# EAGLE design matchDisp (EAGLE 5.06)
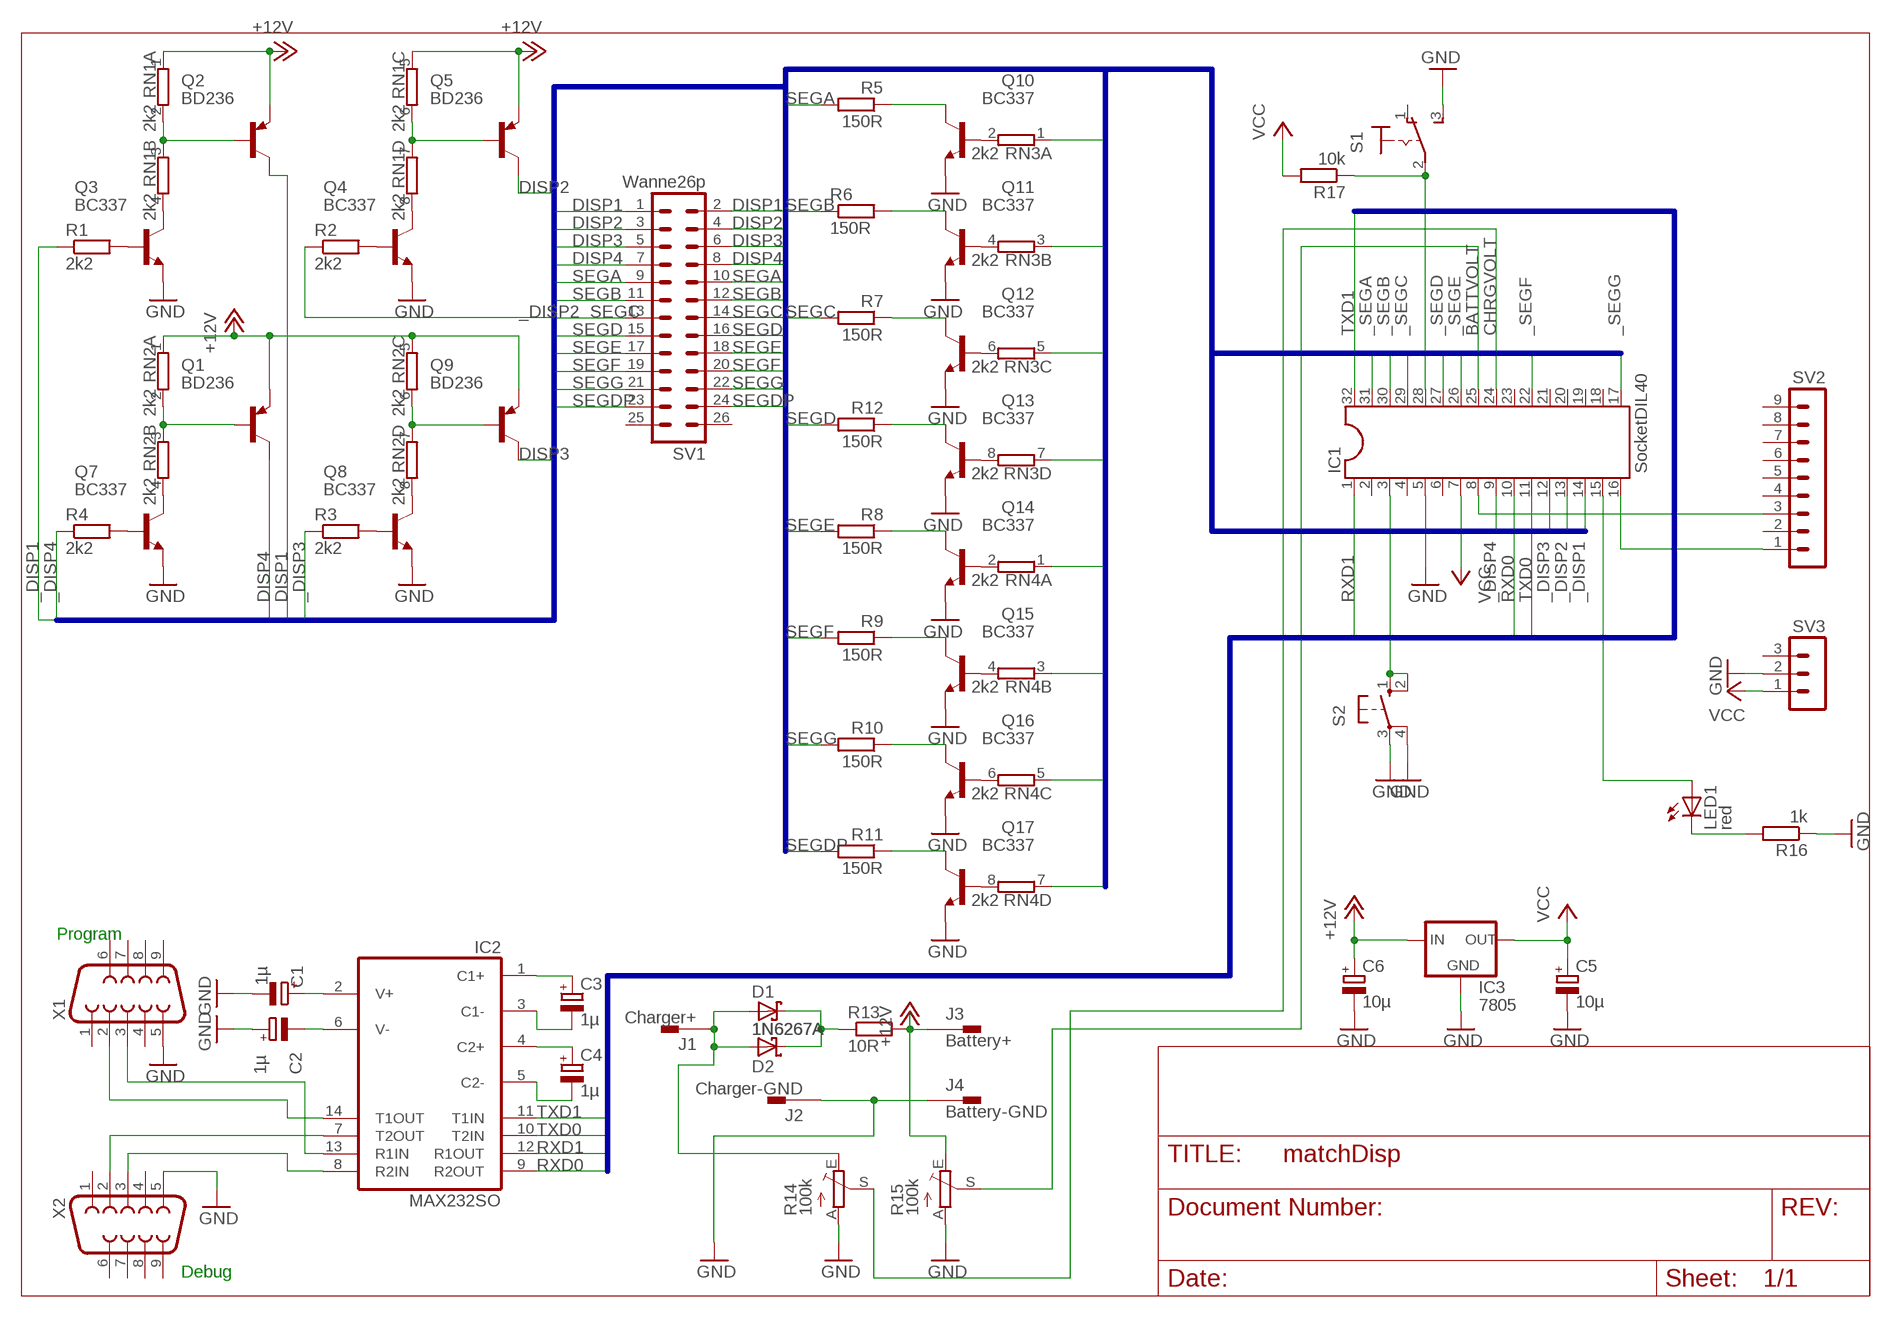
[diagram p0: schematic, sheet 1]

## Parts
C1  1µ  CPOL-EUE2.5-6  [E2,5-6]
C2  1µ  CPOL-EUE2.5-6  [E2,5-6]
C3  1µ  CPOL-EUE2.5-6  [E2,5-6]
C4  1µ  CPOL-EUE2.5-6  [E2,5-6]
C5  10µ  CPOL-EUE2.5-6  [E2,5-6]
C6  10µ  CPOL-EUE2.5-6  [E2,5-6]
D1  1N6267A  [C4111-15]
D2  1N6267A  [C4111-15]
IC1  SocketDIL40  DIL32  [DIL32]
IC2  MAX232SO  [SO16]
IC3  7805  78XXS  [78XXS]
J1  Charger+  PIN262409-1  [62409-1]
J2  Charger-GND  PIN262409-1  [62409-1]
J3  Battery+  PIN262409-1  [62409-1]
J4  Battery-GND  PIN262409-1  [62409-1]
LED1  red  LEDSFH480  [SFH480]
Q1  BD236  [TO126]
Q2  BD236  [TO126]
Q3  BC337  [TO92]
Q4  BC337  [TO92]
Q5  BD236  [TO126]
Q7  BC337  [TO92]
Q8  BC337  [TO92]
Q9  BD236  [TO126]
Q10  BC337  [TO92]
Q11  BC337  [TO92]
Q12  BC337  [TO92]
Q13  BC337  [TO92]
Q14  BC337  [TO92]
Q15  BC337  [TO92]
Q16  BC337  [TO92]
Q17  BC337  [TO92]
R1  2k2  R-EU_0204/2V  [0204V]
R2  2k2  R-EU_0204/2V  [0204V]
R3  2k2  R-EU_0204/2V  [0204V]
R4  2k2  R-EU_0204/2V  [0204V]
R5  150R  R-EU_0204/2V  [0204V]
R6  150R  R-EU_0204/2V  [0204V]
R7  150R  R-EU_0204/2V  [0204V]
R8  150R  R-EU_0204/2V  [0204V]
R9  150R  R-EU_0204/2V  [0204V]
R10  150R  R-EU_0204/2V  [0204V]
R11  150R  R-EU_0204/2V  [0204V]
R12  150R  R-EU_0204/2V  [0204V]
R13  10R  R-EU_0817/22  [P0817/22]
R14  100k  TRIM_EU-B64Y  [B64Y]
R15  100k  TRIM_EU-B64Y  [B64Y]
R16  1k  R-EU_0411/12  [0411/12]
R17  10k  R-EU_0411/12  [0411/12]
RN1  2k2  E4R  [SIL8]
RN2  2k2  E4R  [SIL8]
RN3  2k2  E4R  [SIL8]
RN4  2k2  E4R  [SIL8]
S1  M9040P  [M9040P]
S2  10-XX  [B3F-10XX]
SV1  Wanne26p  ML26  [ML26]
SV2  MA09-1  [MA09-1]
SV3  MA03-1  [MA03-1]
X1  F09VP  [F09VP]
X2  F09VP  [F09VP]

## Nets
+12V: C6.+ IC3.IN J3.A1 Q1.1(E) Q2.1(E) Q5.1(E) Q9.1(E) R13.2 R15.E RN1.1 RN1.5 RN2.1 RN2.5
_DISP1: IC1.14 R1.1
_DISP2: IC1.13 R2.1
_DISP3: IC1.12 R3.1
_DISP4: IC1.9 R4.1
_SEGA: IC1.31 RN3.1
_SEGB: IC1.30 RN3.3
_SEGC: IC1.29 RN3.5
_SEGD: IC1.27 RN3.7
_SEGDP: RN4.7
_SEGE: IC1.26 RN4.1
_SEGF: IC1.22 RN4.3
_SEGG: IC1.17 RN4.5
BATTVOLT: IC1.25 R15.S
CHRGVOLT: IC1.24 R14.S
DISP1: Q2.2(C) SV1.1 SV1.2
DISP2: Q5.2(C) SV1.3 SV1.4
DISP3: Q9.2(C) SV1.5 SV1.6
DISP4: Q1.2(C) SV1.7 SV1.8
GND: C1.- C2.+ C5.- C6.- IC1.5 IC3.GND J2.A1 J4.A1 Q3.1(E) Q4.1(E) Q7.1(E) Q8.1(E) Q10.1(E) Q11.1(E) Q12.1(E) Q13.1(E) Q14.1(E) Q15.1(E) Q16.1(E) Q17.1(E) R14.A R15.A R16.1 S1.3(S) S2.3(P) S2.4(P1) SV3.2 X1.5 X2.5
N$1: IC1.15 LED1.A
N$2: Q3.2(B) R1.2
N$3: Q3.3(C) RN1.4
N$4: LED1.K(C) R16.2
N$5: Q2.3(B) RN1.2 RN1.3
N$6: D1.C D2.C R13.1
N$7: Q4.3(C) RN1.8
N$8: Q5.3(B) RN1.6 RN1.7
N$9: Q13.3(C) R12.1
N$10: C1.+ IC2.2(V+)
N$11: C2.- IC2.6(V-)
N$12: Q1.3(B) RN2.2 RN2.3
N$13: Q4.2(B) R2.2
N$14: Q8.2(B) R3.2
N$15: Q7.2(B) R4.2
N$16: Q10.2(B) RN3.2
N$17: Q11.2(B) RN3.4
N$18: Q12.2(B) RN3.6
N$19: C3.+ IC2.1(C1+)
N$20: Q9.3(B) RN2.6 RN2.7
N$21: C3.- IC2.3(C1-)
N$22: C4.+ IC2.4(C2+)
N$23: Q7.3(C) RN2.4
N$24: Q8.3(C) RN2.8
N$25: Q13.2(B) RN3.8
N$26: Q14.2(B) RN4.2
N$27: Q15.2(B) RN4.4
N$28: Q16.2(B) RN4.6
N$29: Q17.2(B) RN4.8
N$30: Q10.3(C) R5.1
N$31: Q17.3(C) R11.1
N$32: Q16.3(C) R10.1
N$33: Q15.3(C) R9.1
N$34: Q14.3(C) R8.1
N$35: C4.- IC2.5(C2-)
N$36: Q12.3(C) R7.1
N$37: Q11.3(C) R6.2
N$38: IC2.13(R1IN) X1.3
N$39: IC2.14(T1OUT) X1.2
N$40: IC2.7(T2OUT) X2.2
N$41: IC2.8(R2IN) X2.3
N$42: IC1.3 S2.1(S) S2.2(S1)
N$43: IC1.28 R17.1 S1.2(P)
N$44: IC1.16 SV2.1
N$45: IC1.8 SV2.3
N$46: D1.A D2.A J1.A1 R14.E
RXD0: IC1.10 IC2.9(R2OUT)
RXD1: IC1.1 IC2.12(R1OUT)
SEGA: R5.2 SV1.9 SV1.10
SEGB: R6.1 SV1.11 SV1.12
SEGC: R7.2 SV1.13 SV1.14
SEGD: R12.2 SV1.15 SV1.16
SEGDP: R11.2 SV1.23 SV1.24
SEGE: R8.2 SV1.17 SV1.18
SEGF: R9.2 SV1.19 SV1.20
SEGG: R10.2 SV1.21 SV1.22
TXD0: IC1.11 IC2.10(T2IN)
TXD1: IC1.32 IC2.11(T1IN)
VCC: C5.+ IC1.7 IC3.OUT R17.2 SV3.1
Unconnected: IC1.2 IC1.4 IC1.6 IC1.18 IC1.19 IC1.20 IC1.21 IC1.23 J1.A2(1.1) J2.A2(1.1) J3.A2(1.1) J4.A2(1.1) S1.1(O) SV1.25 SV1.26 SV2.2 SV2.4 SV2.5 SV2.6 SV2.7 SV2.8 SV2.9 SV3.3 X1.1 X1.4 X1.6 X1.7 X1.8 X1.9 X2.1 X2.4 X2.6 X2.7 X2.8 X2.9

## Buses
DRVBUS:_DISP1,DISP1,_DISP2,DISP2,_DISP3,DISP3,_DISP4,DISP4,_SEGA,SEGA,_SEGB,SEGB,_SEGC,SEGC,_SEGD,SEGD,_SEGE,SEGE,_SEGF,SEGF,_SEGG,SEGG,_SEGDP,SEGDP
UART:RXD0,TXD0,RXD1,TXD1

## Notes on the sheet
- Program
- Debug

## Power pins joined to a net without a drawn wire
GND: IC2.15(GND)
VCC: IC2.16(VCC)

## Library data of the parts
C1-C6 = rcl:CPOL-EU: POLARIZED CAPACITOR, European symbol
D1 D2 = diode:1N6267A: DIODE
IC1 = ic-package:DIL32: Dual In Line
IC2 = maxim:MAX232: RS232 TRANSEIVER
IC3 = v-reg:78XXS: VOLTAGE REGULATOR
J1-J4 = con-faston:PIN2: Flachstecker Typ Tyco/Electronics/AMP TAB, FASTON
LED1 = led:LED: LED
Q1 Q2 Q5 Q9 = transistor-pnp:BD236: PNP Transistor
Q3 Q7 Q10-Q17 = transistor-npn:BC337*: NPN Transistor
Q4 Q8 = transistor-neu-to92:BC337: NPN TRANSISTOR
R1-R12 R16 R17 = rcl:R-EU_: RESISTOR, European symbol
R13 = resistor:R-EU_: RESISTOR, European symbol
R14 R15 = pot:TRIM_EU-: POTENTIOMETER
RN1-RN4 = resistor-sil:E4R: SIL RESISTOR
S1 = switch:M9040P: TOGGLE SWITCH Marquardt
S2 = switch-omron:10-XX: OMRON SWITCH
SV1 = con-harting-ml:ML26: HARTING
SV2 = con-lstb:MA09-1: PIN HEADER
SV3 = con-lstb:MA03-1: PIN HEADER
X1 X2 = con-subd:F09: SUB-D

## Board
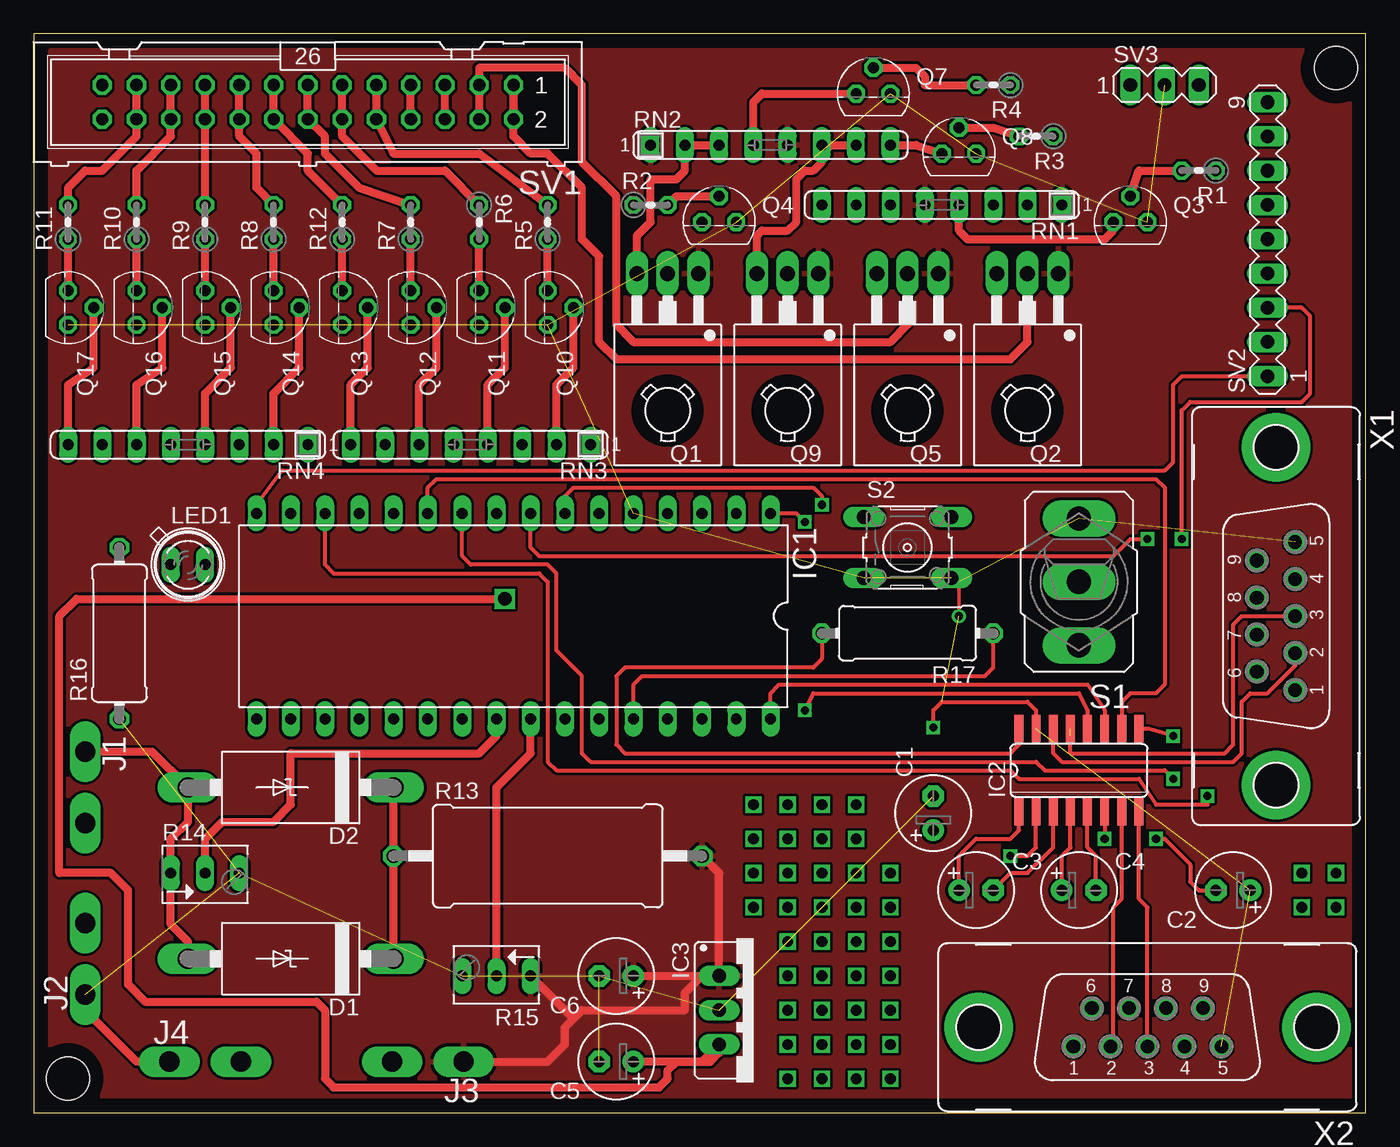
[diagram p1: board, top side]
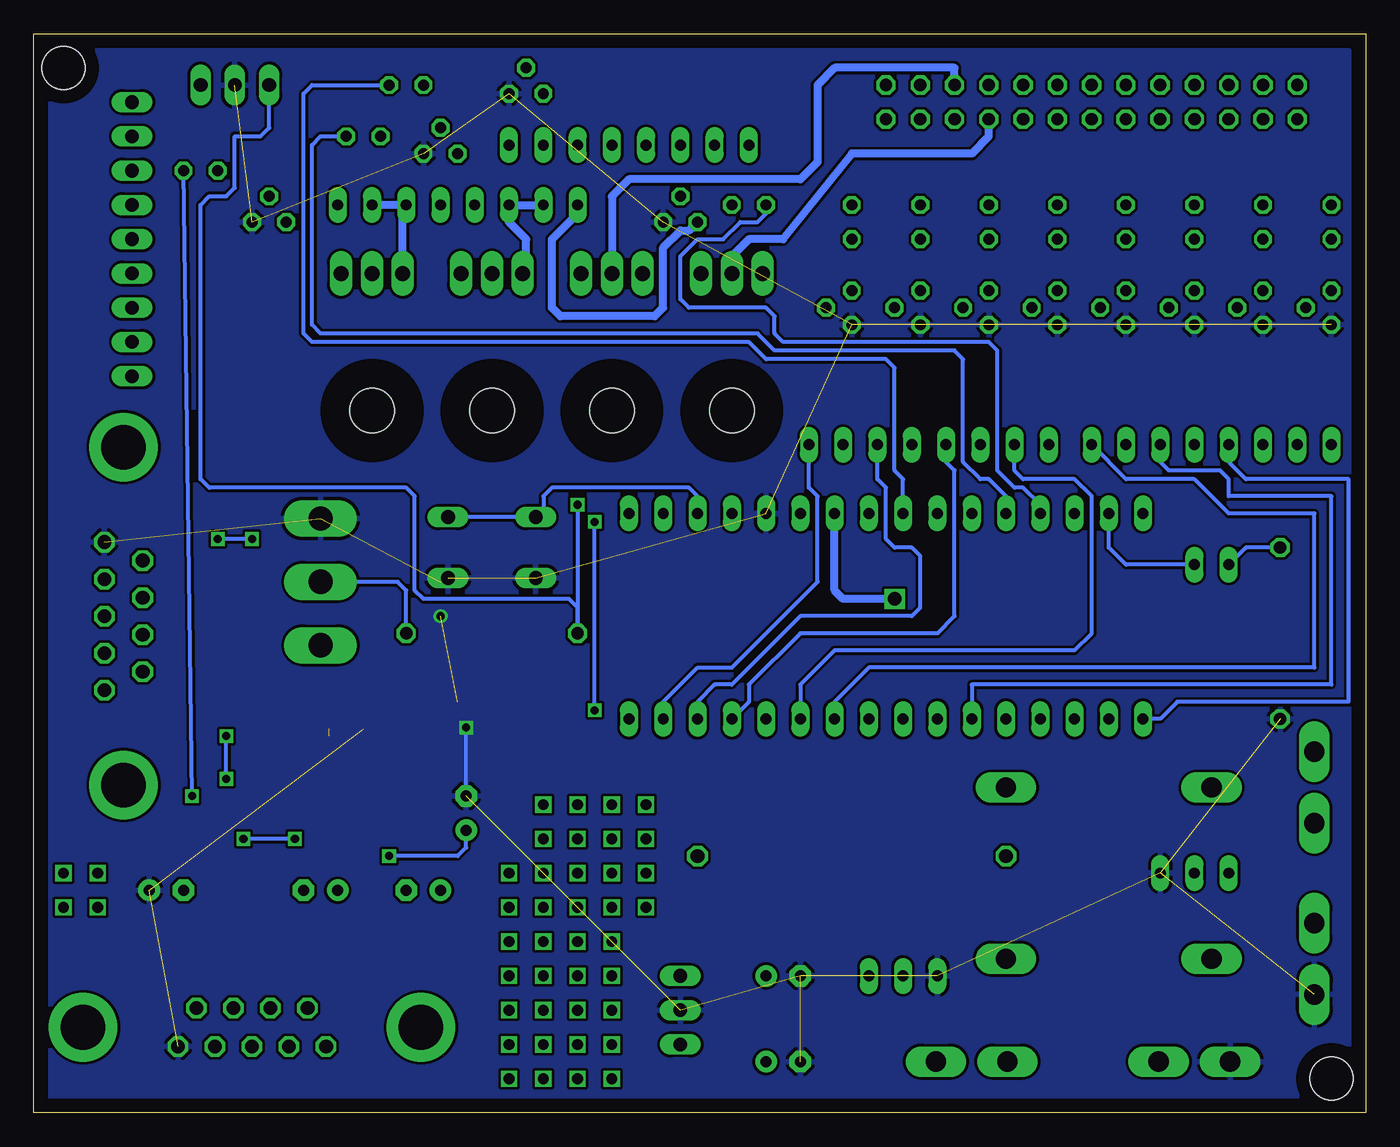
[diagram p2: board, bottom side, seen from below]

Size 98.73 x 80 mm. Coordinates in mm from the lower left corner, seen from the top.
Outline: 0,0 98.73,0 98.73,80 0,80 0,0
Copper layers (1*16): Top 0.035mm / dielectric 1.5mm / Bottom 0.035mm
Design rules "default": minimum track width 10mil, minimum drill 24mil, track to track 8mil, track to pad 8mil, pad to pad 8mil, via to via 8mil, smd to smd 8mil, copper to edge 40mil, drill to drill 8mil, minimum pad ring 10mil, minimum via ring 8mil, stop-mask expansion 4mil, vias tented up to drill 0mil, thermal gap 10mil
Holes 3.2 mm at 2.54,2.54 96.52,77.47

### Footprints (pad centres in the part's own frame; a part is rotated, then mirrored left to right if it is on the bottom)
E2,5-6 = drill 0.813 pad 1.6 round: + -1.27,0 | drill 0.813 pad 1.6 octagon: - 1.27,0
C4111-15 = drill 1.499 long: A 7.62,0; C -7.62,0
DIL32 = drill 0.813 long: 1 -19.05,-7.62; 2 -16.51,-7.62; 3 -13.97,-7.62; 4 -11.43,-7.62; 5 -8.89,-7.62; 6 -6.35,-7.62; 7 -3.81,-7.62; 8 -1.27,-7.62; 9 1.27,-7.62; 10 3.81,-7.62; 11 6.35,-7.62; 12 8.89,-7.62; 13 11.43,-7.62; 14 13.97,-7.62; 15 16.51,-7.62; 16 19.05,-7.62; 17 19.05,7.62; 18 16.51,7.62; 19 13.97,7.62; 20 11.43,7.62; 21 8.89,7.62; 22 6.35,7.62; 23 3.81,7.62; 24 1.27,7.62; 25 -1.27,7.62; 26 -3.81,7.62; 27 -6.35,7.62; 28 -8.89,7.62; 29 -11.43,7.62; 30 -13.97,7.62; 31 -16.51,7.62; 32 -19.05,7.62
SO16 = smd 0.66 x 2.032: 1 -4.445,-3.073; 2 -3.175,-3.073; 3 -1.905,-3.073; 4 -0.635,-3.073; 5 0.635,-3.073; 6 1.905,-3.073; 7 3.175,-3.073; 8 4.445,-3.073; 9 4.445,3.073; 10 3.175,3.073; 11 1.905,3.073; 12 0.635,3.073; 13 -0.635,3.073; 14 -1.905,3.073; 15 -3.175,3.073; 16 -4.445,3.073
78XXS = drill 1.016 long: GND 0,-2.54; IN -2.54,-2.54; OUT 2.54,-2.54
62409-1 = drill 1.5 pad 1.9 long: A1 -2.65,0; A2 2.65,0
SFH480 = drill 0.813 long: A 1.27,0; K -1.27,0
TO126 = drill 1.118 long: 1 -2.286,-5.08; 2 0,-5.08; 3 2.286,-5.08 | hole 3.302: 0,5.08
TO92 = drill 0.813 octagon: 1 1.27,0; 2 0,1.905; 3 -1.27,0
0204V = drill 0.813 octagon: 1 -1.27,0; 2 1.27,0
P0817/22 = drill 1.016 octagon: 1 -11.43,0; 2 11.43,0
B64Y = drill 0.813 long: A 2.54,0; E -2.54,0; S 0,0
0411/12 = drill 0.914 octagon: 1 -6.35,0; 2 6.35,0
SIL8 = drill 0.813 long: 1 -8.89,0; 2 -6.35,0; 3 -3.81,0; 4 -1.27,0; 5 1.27,0; 6 3.81,0; 7 6.35,0; 8 8.89,0
M9040P = drill 1.803 long: 1 0,4.699; 2 0,0; 3 0,-4.699
B3F-10XX = drill 1.016 long: 1 -3.251,2.261; 2 3.251,2.261; 3 -3.251,-2.261; 4 3.251,-2.261
ML26 = drill 0.914 octagon: 1 -15.24,-1.27; 2 -15.24,1.27; 3 -12.7,-1.27; 4 -12.7,1.27; 5 -10.16,-1.27; 6 -10.16,1.27; 7 -7.62,-1.27; 8 -7.62,1.27; 9 -5.08,-1.27; 10 -5.08,1.27; 11 -2.54,-1.27; 12 -2.54,1.27; 13 0,-1.27; 14 0,1.27; 15 2.54,-1.27; 16 2.54,1.27; 17 5.08,-1.27; 18 5.08,1.27; 19 7.62,-1.27; 20 7.62,1.27; 21 10.16,-1.27; 22 10.16,1.27; 23 12.7,-1.27; 24 12.7,1.27; 25 15.24,-1.27; 26 15.24,1.27
MA09-1 = drill 1.016 long: 1 -10.16,0; 2 -7.62,0; 3 -5.08,0; 4 -2.54,0; 5 0,0; 6 2.54,0; 7 5.08,0; 8 7.62,0; 9 10.16,0
MA03-1 = drill 1.016 long: 1 -2.54,0; 2 0,0; 3 2.54,0
F09VP = drill 1.016 octagon: 1 5.486,1.422; 2 2.743,1.422; 3 0,1.422; 4 -2.743,1.422; 5 -5.486,1.422; 6 4.115,-1.422; 7 1.372,-1.422; 8 -1.372,-1.422; 9 -4.115,-1.422 | drill 3.302 pad 5.08 round: G1 -12.522,0; G2 12.522,0

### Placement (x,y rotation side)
C1  66.67,22.23 90 top
C2  88.9,16.51 180 top
C3  69.85,16.51 0 top
C4  77.47,16.51 0 top
C5  43.18,3.81 180 top
C6  43.18,10.16 180 top
D1  19.05,11.43 180 top
D2  19.05,24.13 180 top
IC1  35.56,36.83 180 top
IC2  77.47,25.4 0 top
IC3  53.34,7.62 270 top
J1  3.81,24.13 270 top
J2  3.81,11.43 90 top
J3  29.21,3.81 180 top
J4  12.7,3.81 0 top
LED1  11.43,40.64 0 top
Q1  46.99,57.15 180 top
Q2  73.66,57.15 180 top
Q3  81.28,66.04 0 top
Q4  50.8,66.04 0 top
Q5  64.77,57.15 180 top
Q7  62.23,75.56 0 top
Q8  68.58,71.12 0 top
Q9  55.88,57.15 180 top
Q10  38.1,59.69 270 top
Q11  33.02,59.69 270 top
Q12  27.94,59.69 270 top
Q13  22.86,59.69 270 top
Q14  17.78,59.69 270 top
Q15  12.7,59.69 270 top
Q16  7.62,59.69 270 top
Q17  2.54,59.69 270 top
R1  86.36,69.85 180 top
R2  45.72,67.31 0 top
R3  74.3,72.39 180 top
R4  71.12,76.2 180 top
R5  38.1,66.04 90 top
R6  33.02,66.04 270 top
R7  27.94,66.04 90 top
R8  17.78,66.04 90 top
R9  12.7,66.04 90 top
R10  7.62,66.04 90 top
R11  2.54,66.04 90 top
R12  22.86,66.04 90 top
R13  38.1,19.05 0 top
R14  12.7,17.78 0 top
R15  34.29,10.16 180 top
R16  6.35,35.56 90 top
R17  64.77,35.56 180 top
RN1  67.31,67.31 180 top
RN2  54.61,71.75 0 top
RN3  32.38,49.53 180 top
RN4  11.43,49.53 180 top
S1  77.47,39.37 180 top
S2  64.77,41.91 0 top
SV1  20.32,74.93 180 top
SV2  91.44,64.77 90 top
SV3  83.82,76.2 0 top
X1  92.08,36.83 270 top
X2  82.55,6.35 180 top

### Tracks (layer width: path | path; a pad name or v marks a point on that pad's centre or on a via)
+12V
  Top 0.61: C6.+ IC3.IN 50.8,17.78 R13.2 | 49.53,10.16 48.26,8.89 48.26,7.62 40.64,7.62 40.01,6.99 | 40.01,6.99 39.37,6.35 39.37,5.08 38.1,3.81 J3.A1 31.75,3.81 | 40.01,6.99 R15.E
  pour Top: 1.27,78.74 97.79,78.74 97.79,1.27 1.27,1.27
_DISP1  (via drill 0.6)
  Top 0.305: IC1.14 21.59,40.64 22.23,40.01 37.47,40.01 38.1,39.37 38.1,26.04 38.73,25.4 72.39,25.4 73.03,24.77 81.92,24.77 83.19,22.86 87,22.86 v87,23.5
  Bottom 0.305: v87,23.5 R1.1
_DISP2
  Bottom 0.305: R2.1 44.45,66.67 45.09,66.04 46.35,66.04 47.62,64.77 49.53,64.77 50.8,63.5 50.8,60.33 50.16,59.69 44.45,59.69 43.81,59.05 43.81,57.78 43.18,57.15 27.94,57.15 27.3,56.52 27.3,47.62 26.04,46.35 25.4,46.35 24.13,45.09 IC1.13
_DISP3
  Bottom 0.305: IC1.12 26.67,45.72 27.94,46.99 28.57,46.99 29.84,48.26 29.84,55.88 30.48,56.52 43.81,56.52 45.09,57.78 77.47,57.78 78.11,58.42 78.11,71.75 77.47,72.39 R3.1
_DISP4
  Bottom 0.305: IC1.9 34.29,46.99 34.92,47.62 34.92,55.24 35.56,55.88 44.45,55.88 45.72,57.15 78.11,57.15 78.74,57.78 78.74,75.56 78.11,76.2 R4.1
_SEGA
  Bottom 0.305: RN3.1 41.27,46.35 40.64,45.72 40.64,39.37 46.99,33.02 49.53,33.02 52.07,30.48 IC1.31
_SEGB
  Bottom 0.305: RN3.3 36.2,46.99 35.56,46.35 35.56,42.55 34.92,41.91 33.66,41.91 33.02,41.27 33.02,37.47 33.66,36.83 41.91,36.83 46.99,31.75 48.26,31.75 49.53,30.48 IC1.30
_SEGC
  Bottom 0.305: RN3.5 31.11,48.26 30.48,47.62 30.48,36.83 31.75,35.56 41.91,35.56 45.72,31.75 45.72,30.48 IC1.29
_SEGD
  Bottom 0.305: RN3.7 26.04,47.62 25.4,46.99 21.59,46.99 20.32,45.72 20.32,35.56 21.59,34.29 39.37,34.29 41.91,31.75 IC1.27
_SEGE
  Bottom 0.305: RN4.1 17.78,46.99 12.7,46.99 10.16,44.45 3.81,44.45 3.81,33.02 36.83,33.02 39.37,30.48 IC1.26
_SEGF
  Bottom 0.305: RN4.3 15.24,48.26 14.61,47.62 10.79,47.62 10.16,46.99 10.16,45.72 2.54,45.72 2.54,31.75 29.21,31.75 IC1.22
_SEGG
  Bottom 0.305: RN4.5 10.16,48.26 8.89,46.99 1.27,46.99 1.27,30.48 2.54,30.48 | 2.54,30.48 3.81,30.48 | 2.54,30.48 13.97,30.48 15.24,29.21 IC1.17
BATTVOLT
  Top 0.61: IC1.25 36.83,26.67 34.29,24.13 R15.S
CHRGVOLT
  Top 0.61: R14.S 12.7,20.32 13.97,21.59 17.78,21.59 19.05,22.86 19.05,26.67 33.02,26.67 34.29,27.94 IC1.24
DISP1
  Top 0.61: SV1.2 SV1.1 35.56,72.39 36.83,71.12 38.1,71.12 40.64,68.58 40.64,64.77 41.91,63.5 41.91,57.15 43.18,55.88 72.39,55.88 73.66,57.15 Q2.2
DISP2
  Top 0.61: SV1.4 SV1.3 33.02,77.47 39.37,77.47 40.64,76.2 40.64,70.48 43.18,67.94 43.18,58.42 44.45,57.15 63.5,57.15 64.77,58.42 Q5.2
DISP3
  Top 0.61: SV1.6 SV1.5
  Bottom 0.61: SV1.5 30.48,77.47 39.37,77.47 40.64,76.2 40.64,70.48 41.91,69.22 54.61,69.22 55.88,67.94 Q9.2
DISP4
  Top 0.61: SV1.8 SV1.7 SV1.8
  Bottom 0.61: SV1.8 27.94,72.39 29.21,71.12 38.1,71.12 43.18,64.77 45.72,64.77 46.99,63.5 Q1.2
GND  (via drill 0.6, 0.61)  (27 unrouted)
  Top 0.254: v68.58,36.83 68.58,39.37 S2.4
  Top 0.305: IC2.15 74.3,29.84 73.66,30.48 67.31,30.48 66.67,29.84 v66.67,28.57
  Top 0.61: J2.A1 3.81,7.62 7.62,3.81 J4.A1
  Bottom 0.305: C1.- v66.67,28.57
  pour Bottom: 1.27,78.74 97.79,78.74 97.79,1.27 1.27,1.27
N$1
  Bottom 0.305: IC1.15 19.05,41.91 17.78,40.64 LED1.A
N$2
  Top 0.61: R1.2 81.92,69.85 Q3.2
N$3
  Top 0.61: Q3.3 80.01,65.41 79.38,64.77 69.22,64.77 68.58,65.41 RN1.4
N$4
  Bottom 0.305: LED1.K 8.89,41.91 R16.2
N$5
  Bottom 0.61: Q2.3 71.37,67.06 RN1.3 RN1.2
N$6
  Top 0.61: D2.C R13.1 D1.C
N$7
  Bottom 0.61: RN1.8 58.42,66.67 60.33,64.77 60.33,59.69 59.69,59.05 52.7,59.05 52.07,59.69 52.07,64.14 50.8,65.41 50.16,65.41 Q4.3
N$8
  Bottom 0.61: RN1.7 RN1.6 63.5,66.04 62.23,64.77 62.23,62.48 Q5.3
N$9
  Top 0.61: Q13.3 R12.1
N$10  (via drill 0.6)
  Top 0.305: IC2.2 74.3,19.68 73.66,19.05 v72.39,19.05
  Bottom 0.305: v72.39,19.05 67.31,19.05 66.67,19.68 C1.+
N$11  (via drill 0.6)
  Top 0.305: IC2.6 v79.38,20.32 | C2.- 86.36,16.51 85.72,17.14 85.72,18.41 83.82,20.32 v83.19,20.32
  Bottom 0.305: v79.38,20.32 v83.19,20.32
N$12
  Top 0.61: Q1.3 44.7,65.02 45.72,66.04 45.72,69.22 47.62,69.22 48.26,69.85 48.26,71.12 | 48.26,71.12 RN2.2 | RN2.3 48.9,71.75 48.26,71.12
N$13
  Top 0.61: Q4.2 47.62,67.94 R2.2
N$14
  Top 0.61: R3.2 71.12,73.03 Q8.2
N$15
  Top 0.61: R4.2 66.04,76.2 66.04,76.83 65.41,77.47 Q7.2
N$16
  Top 0.61: Q10.2 40.01,55.24 38.73,53.98 RN3.2
N$17
  Top 0.61: Q11.2 34.92,55.24 33.66,53.98 RN3.4
N$18
  Top 0.61: Q12.2 29.84,55.24 28.57,53.98 RN3.6
N$19
  Top 0.305: IC2.1 73.03,20.95 72.39,20.32 69.85,20.32 68.58,19.05 C3.+
N$20
  Top 0.61: Q9.3 53.59,65.02 53.98,65.41 55.88,65.41 56.52,66.04 56.52,69.22 57.15,69.85 57.78,69.85 58.42,70.48 58.42,71.12 | 58.42,71.12 RN2.6 | RN2.7 59.05,71.75 58.42,71.12
N$21
  Top 0.305: IC2.3 75.56,19.68 73.66,17.78 72.39,17.78 C3.-
N$22
  Top 0.305: IC2.4 76.83,19.68 76.2,19.05 C4.+
N$23
  Top 0.61: Q7.3 53.98,75.56 53.34,74.93 RN2.4
N$24
  Top 0.61: Q8.3 65.41,71.75 RN2.8
N$25
  Top 0.61: Q13.2 24.77,55.24 23.5,53.98 RN3.8
N$26
  Top 0.61: Q14.2 19.68,55.24 17.78,53.34 RN4.2
N$27
  Top 0.61: Q15.2 14.61,55.24 12.7,53.34 RN4.4
N$28
  Top 0.61: Q16.2 9.53,55.24 7.62,53.98 RN4.6
N$29
  Top 0.61: Q17.2 4.45,55.24 2.54,53.98 RN4.8
N$30
  Top 0.61: Q10.3 R5.1
N$31
  Top 0.61: Q17.3 R11.1
N$32
  Top 0.61: Q16.3 R10.1
N$33
  Top 0.61: Q15.3 R9.1
N$34
  Top 0.61: Q14.3 R8.1
N$35
  Top 0.305: IC2.5 78.11,19.68 78.74,19.05 C4.-
N$36
  Top 0.61: Q12.3 R7.1
N$37
  Top 0.61: Q11.3 R6.2
N$38  (1 unrouted)
  Top 0.305: X1.3 89.53,36.83 88.9,36.2 88.9,27.3 88.27,26.67 76.83,26.67 76.83,27.94
N$39
  Top 0.305: X1.2 93.5,33.17 91.44,31.11 90.17,31.11 89.53,30.48 89.53,26.67 88.9,26.04 76.2,26.04 75.56,26.67 IC2.14
N$40
  Top 0.305: IC2.7 80.64,15.88 80.01,15.24 80.01,5.13 X2.2
N$41
  Top 0.305: IC2.8 81.92,15.88 82.55,15.24 X2.3
N$42
  Bottom 0.305: IC1.3 49.53,45.72 50.16,46.35 60.33,46.35 60.96,45.72 60.96,44.73 S2.1 S2.2
N$43
  Top 0.305: IC1.28 44.45,31.75 45.09,32.38 70.48,32.38 71.12,33.02 R17.1
  Bottom 0.305: S1.2 71.75,39.37 71.12,38.73 R17.1
N$44
  Top 0.305: IC1.16 16.51,45.09 18.41,47.62 83.82,47.62 84.45,48.26 84.45,53.98 85.09,54.61 87,54.61 88.9,54.61 SV2.1
N$45  (via drill 0.6)
  Top 0.305: IC1.8 36.83,41.91 37.47,41.27 80.01,41.27 81.28,42.55 v82.55,42.55 | SV2.3 93.98,59.69 94.61,59.05 94.61,53.34 93.98,52.7 85.72,52.7 85.09,52.07 v85.09,42.55
  Bottom 0.305: v82.55,42.55 v85.09,42.55
N$46
  Top 0.61: J1.A1 8.78,26.78 D2.A 11.43,21.59 10.16,20.32 R14.E 10.16,13.97 11.43,12.7 D1.A
N$47  (via drill 0.8)
  other vias: 58.42,22.86
N$48  (via drill 0.8)
  other vias: 58.42,20.32
N$49  (via drill 0.8)
  other vias: 58.42,17.78
N$50  (via drill 0.8)
  other vias: 55.88,22.86
N$51  (via drill 0.8)
  other vias: 53.34,22.86
N$52  (via drill 0.8)
  other vias: 53.34,20.32
N$53  (via drill 0.8)
  other vias: 55.88,20.32
N$54  (via drill 0.8)
  other vias: 53.34,17.78
N$55  (via drill 0.8)
  other vias: 55.88,17.78
N$56  (via drill 0.8)
  other vias: 53.34,15.24
N$57  (via drill 0.8)
  other vias: 55.88,15.24
N$58  (via drill 0.8)
  other vias: 58.42,15.24
N$59  (via drill 0.8)
  other vias: 58.42,12.7
N$60  (via drill 0.8)
  other vias: 55.88,12.7
N$61  (via drill 0.8)
  other vias: 55.88,10.16
N$62  (via drill 0.8)
  other vias: 55.88,7.62
N$63  (via drill 0.8)
  other vias: 55.88,5.08
N$64  (via drill 0.8)
  other vias: 55.88,2.54
N$65  (via drill 0.8)
  other vias: 58.42,2.54
N$66  (via drill 0.8)
  other vias: 58.42,5.08
N$67  (via drill 0.8)
  other vias: 58.42,7.62
N$68  (via drill 0.8)
  other vias: 58.42,10.16
N$69  (via drill 0.8)
  other vias: 60.96,10.16
N$70  (via drill 0.8)
  other vias: 60.96,7.62
N$71  (via drill 0.8)
  other vias: 60.96,5.08
N$72  (via drill 0.8)
  other vias: 60.96,2.54
N$73  (via drill 0.8)
  other vias: 63.5,2.54
N$74  (via drill 0.8)
  other vias: 63.5,5.08
N$75  (via drill 0.8)
  other vias: 63.5,7.62
N$76  (via drill 0.8)
  other vias: 63.5,10.16
N$77  (via drill 0.8)
  other vias: 60.96,20.32
N$78  (via drill 0.8)
  other vias: 60.96,17.78
N$79  (via drill 0.8)
  other vias: 60.96,15.24
N$80  (via drill 0.8)
  other vias: 63.5,15.24
N$81  (via drill 0.8)
  other vias: 63.5,17.78
N$82  (via drill 0.8)
  other vias: 60.96,12.7
N$83  (via drill 0.8)
  other vias: 63.5,12.7
N$84  (via drill 0.8)
  other vias: 60.96,22.86
N$85  (via drill 0.8)
  other vias: 93.98,17.78
N$86  (via drill 0.8)
  other vias: 96.52,17.78
N$87  (via drill 0.8)
  other vias: 93.98,15.24
N$88  (via drill 0.8)
  other vias: 96.52,15.24
RXD0  (via drill 0.6)
  Top 0.305: 81.92,28.57 IC2.9 82.65,28.47 v84.45,27.94 | IC1.10 31.75,41.27 32.38,40.64 38.1,40.64 38.73,40.01 38.73,34.29 40.64,32.38 40.64,26.67 41.27,26.04 74.3,26.04 74.93,25.4 83.82,25.4 v84.45,24.77
  Bottom 0.305: v84.45,24.77 v84.45,27.94
RXD1  (via drill 0.6)
  Top 0.305: IC1.1 56.52,44.45 v57.15,43.81 | IC2.12 78.11,29.84 77.47,31.11 57.78,31.11 v57.15,29.84
  Bottom 0.305: v57.15,29.84 v57.15,43.81
SEGA
  Top 0.61: R5.2 33.02,71.12 26.67,71.12 SV1.10 SV1.9
SEGB
  Top 0.61: R6.1 30.48,69.85 25.4,69.85 22.86,72.39 SV1.12 SV1.11
SEGC
  Top 0.61: R7.2 24.13,68.58 21.59,71.12 21.59,72.39 SV1.14 SV1.13
SEGD
  Top 0.61: R12.2 20.32,69.85 20.32,71.12 SV1.16 SV1.15
SEGDP
  Top 0.61: R11.2 2.54,68.58 3.81,69.85 5.08,69.85 7.62,72.39 SV1.24 SV1.23
SEGE
  Top 0.61: R8.2 16.51,68.58 16.51,71.12 15.24,72.39 SV1.18 SV1.17
SEGF
  Top 0.61: R9.2 SV1.20 SV1.19
SEGG
  Top 0.61: R10.2 7.62,69.85 10.16,72.39 SV1.22 SV1.21
TXD0
  Top 0.305: IC2.10 80.64,30.48 81.28,31.11 83.19,31.11 83.82,31.75 83.82,46.35 83.19,46.99 29.84,46.99 29.21,46.35 IC1.11
TXD1
  Top 0.305: IC1.32 54.61,31.11 55.24,31.75 78.11,31.75 79.38,29.84 IC2.11
VCC  (via drill 0.6, 1)
  Top 0.305: IC2.16 73.03,27.3 72.39,26.67 43.81,26.67 43.18,27.3 43.18,32.38 43.81,33.02 57.78,33.02 58.42,33.66 R17.2 | IC1.7 39.37,45.72 40.01,46.35 57.78,46.35 58.42,45.72 v58.42,45.09
  Top 0.61: C5.+ 49.53,3.81 IC3.OUT 50.8,4.45 50.16,3.81 47.62,3.81 46.99,3.17 46.99,2.54 46.35,1.91 22.23,1.91 21.59,2.54 21.59,7.62 20.95,8.26 8.26,8.26 6.99,9.53 6.99,16.51 5.71,17.78 1.91,17.78 1.91,36.83 3.17,38.1 v34.92,38.1
  Bottom 0.305: v58.42,45.09 R17.2 58.42,37.47 59.05,38.1 69.85,38.1 70.48,38.73 70.48,45.72 71.12,46.35 85.72,46.35 86.36,46.99 86.36,67.31 85.72,67.94 84.45,67.94 83.82,68.58 83.82,72.39 81.92,72.39 81.28,73.03 SV3.1
  Bottom 0.61: IC1.7 39.37,38.73 38.73,38.1 v34.92,38.1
